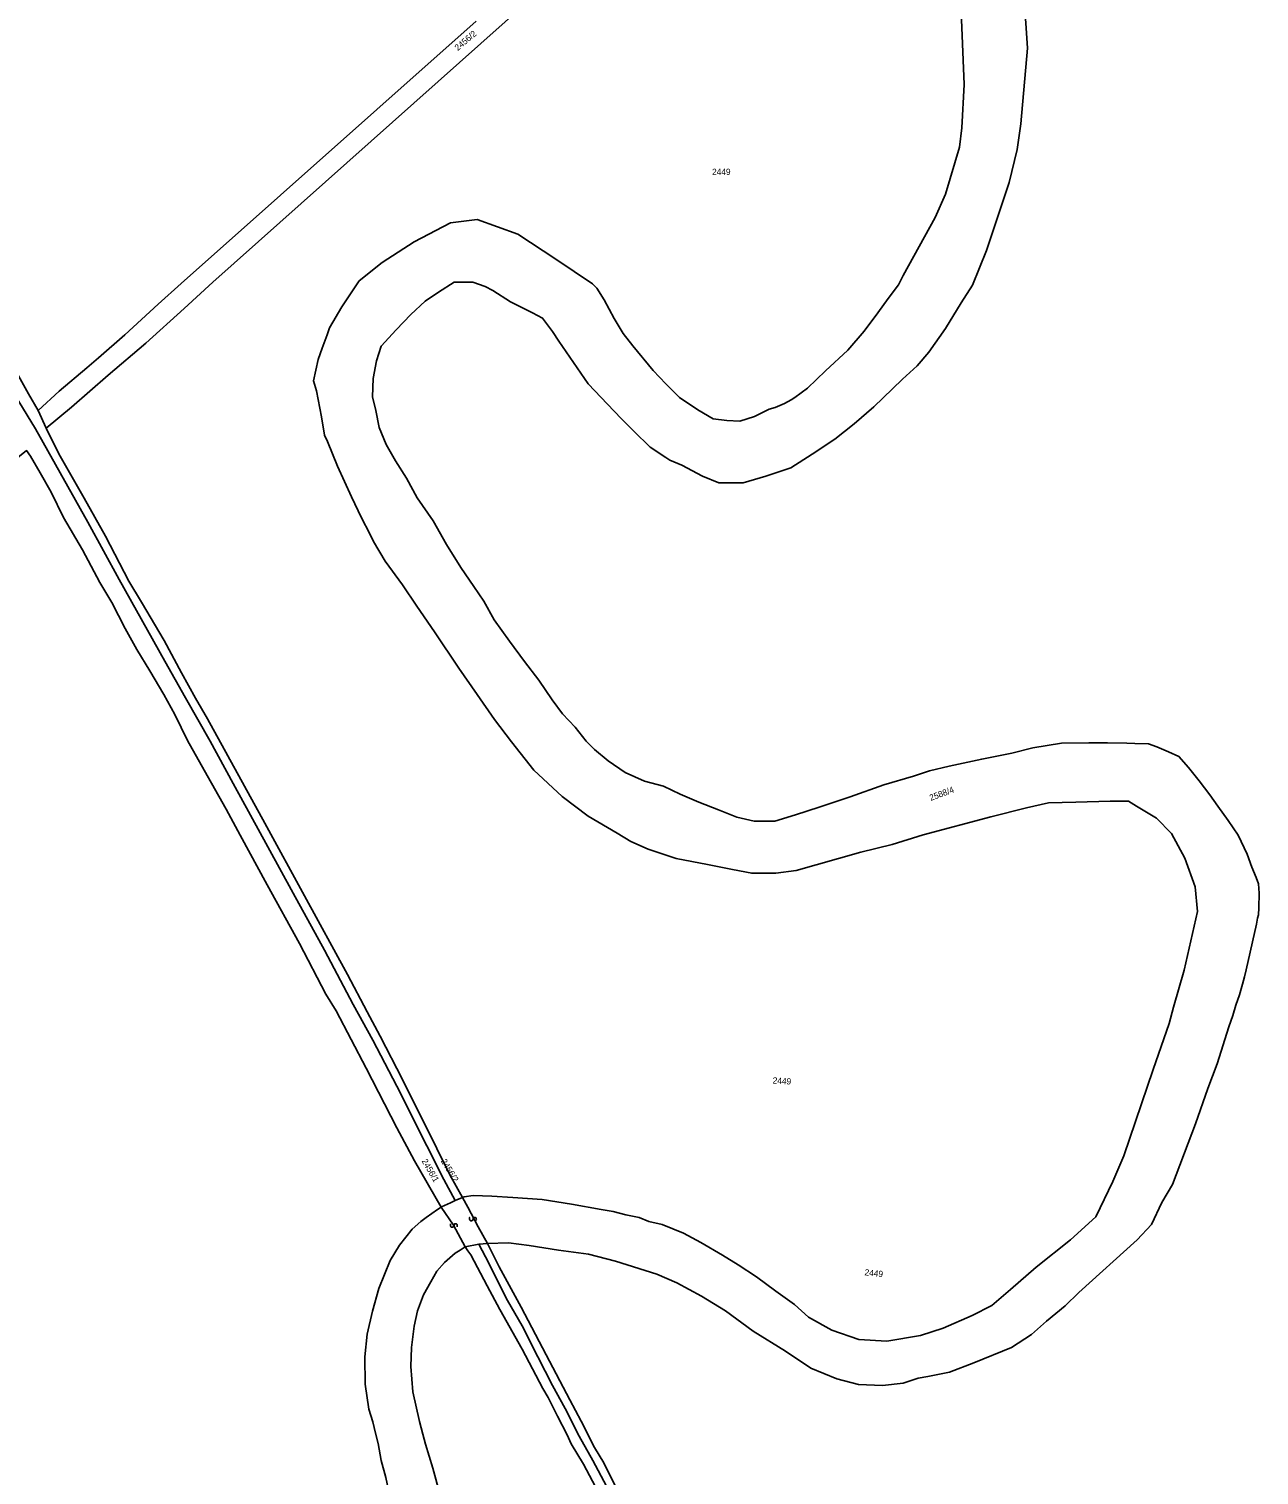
# Model space of a CAD drawing. Extents: x -581999 to -572728, y -1219553 to -1212032.
# Drawn here: x -579464.7 to -579068.9, y -1218458.9 to -1217993.5 of the extents above; entities that cross this region are included whole.
import ezdxf

# ---------------------------------------------------------------- set-up
doc = ezdxf.new("R2010")
doc.units = 0
for name, color, linetype in [('Vrstva 1', 7, 'Continuous'), ('Vrstva 2', 7, 'Continuous'), ('Vrstva 4', 7, 'Continuous'), ('Vrstva 6', 7, 'Continuous')]:
    doc.layers.add(name, color=color, linetype=linetype)

msp = doc.modelspace()

# ---------------------------------------------------------------- linework, layer by layer
at = {"layer": 'Vrstva 1'}
for points in [[(-579161.09, -1218075.938), (-579156.657, -1218064.819), (-579149.279, -1218042.907), (-579146.792, -1218032.236), (-579145.521, -1218023.983), (-579143.409, -1217999.667), (-579144.466, -1217983.535), (-579148.128, -1217948.757), (-579150.946, -1217930.34), (-579153.893, -1217893.376), (-579156.349, -1217870.625), (-579157.124, -1217855.601)], [(-579178.607, -1217874.873), (-579268.374, -1217952.683), (-579405.508, -1218074.987)], [(-579178.607, -1217874.873), (-579177.031, -1217891.385), (-579176.324, -1217904.018), (-579172.693, -1217934.703), (-579172.403, -1217941.208), (-579164.664, -1217990.437), (-579163.787, -1218011.317), (-579164.505, -1218025.247), (-579165.33, -1218031.517), (-579169.824, -1218046.668), (-579173.108, -1218054.19), (-579183.442, -1218072.847), (-579184.956, -1218075.792)], [(-579320.774, -1217990.946), (-579415.781, -1218075.436)], [(-579358.459, -1218074.552), (-579351.068, -1218068.621), (-579340.799, -1218061.98), (-579329.104, -1218055.892), (-579320.546, -1218054.785), (-579307.424, -1218059.49), (-579295.159, -1218067.514), (-579283.394, -1218075.535)], [(-579327.561, -1218370.487), (-579331.193, -1218363.708), (-579336.694, -1218352.936), (-579346.308, -1218333.73), (-579354.031, -1218318.856), (-579360.378, -1218307.469), (-579369.629, -1218289.907), (-579379.679, -1218271.647), (-579387.825, -1218256.67), (-579398.991, -1218236.341), (-579406.396, -1218222.697), (-579414.33, -1218208.746), (-579420.994, -1218196.948), (-579435.645, -1218170.674), (-579445.801, -1218152.209), (-579452.148, -1218140.72), (-579462.574, -1218122.122), (-579471.778, -1218107.042), (-579481.903, -1218087.8), (-579488.885, -1218075.387)], [(-579484.555, -1218075.2), (-579479.794, -1218083.92), (-579472.813, -1218096.64), (-579464.878, -1218110.899), (-579461.705, -1218116.234)], [(-579461.705, -1218116.234), (-579454.984, -1218110.07), (-579446.098, -1218102.581), (-579442.289, -1218099.298), (-579433.826, -1218091.912), (-579423.142, -1218082.064), (-579415.781, -1218075.436)], [(-579405.508, -1218074.987), (-579414.817, -1218083.399), (-579427.088, -1218094.58), (-579439.254, -1218104.839), (-579450.996, -1218115.2), (-579459.173, -1218121.913)], [(-579364.049, -1218082.86), (-579358.459, -1218074.552)], [(-579327.853, -1218074.999), (-579332.976, -1218078.144), (-579337.205, -1218081.073), (-579341.888, -1218085.319), (-579346.57, -1218090.298), (-579351.404, -1218095.57), (-579352.914, -1218100.256), (-579353.972, -1218105.967), (-579354.123, -1218111.824), (-579353.065, -1218116.217), (-579352.008, -1218121.782), (-579349.742, -1218127.2), (-579346.721, -1218132.472), (-579343.247, -1218138.036), (-579339.773, -1218144.333), (-579334.69, -1218151.818), (-579330.31, -1218159.433), (-579325.778, -1218166.755), (-579321.549, -1218172.905), (-579318.377, -1218177.591), (-579315.054, -1218183.595), (-579310.069, -1218190.477), (-579305.236, -1218197.067), (-579300.704, -1218203.071), (-579296.324, -1218209.368), (-579293.001, -1218213.907), (-579288.922, -1218218.154), (-579285.448, -1218222.693), (-579282.729, -1218225.329)], [(-579327.853, -1218074.999), (-579321.87, -1218074.999), (-579317.958, -1218076.338), (-579315.481, -1218077.673)], [(-579224.662, -1218115.246), (-579226.506, -1218115.879), (-579231.311, -1218118.21), (-579235.974, -1218119.718), (-579240.148, -1218119.515), (-579244.528, -1218118.929), (-579249.513, -1218116), (-579255.404, -1218112.047), (-579259.784, -1218107.654), (-579263.863, -1218103.407), (-579270.404, -1218095.45), (-579273.562, -1218091.472), (-579276.446, -1218086.664), (-579279.618, -1218080.66), (-579282.034, -1218076.853), (-579283.394, -1218075.535)], [(-579315.481, -1218077.673), (-579309.742, -1218081.334), (-579302.642, -1218084.849), (-579299.422, -1218086.536), (-579296.298, -1218090.853), (-579294.183, -1218093.928), (-579284.745, -1218107.682), (-579278.552, -1218114.272), (-579274.171, -1218118.811), (-579270.093, -1218122.911), (-579264.806, -1218128.037), (-579259.822, -1218131.405), (-579258.462, -1218132.283), (-579254.686, -1218133.894), (-579248.018, -1218137.384), (-579242.731, -1218139.581), (-579234.877, -1218139.581), (-579227.626, -1218137.384), (-579219.621, -1218134.748), (-579212.673, -1218130.355), (-579205.422, -1218125.523), (-579199.229, -1218120.544), (-579192.885, -1218115.126), (-579186.843, -1218109.268), (-579183.671, -1218106.193), (-579178.914, -1218101.857), (-579175.137, -1218097.464), (-579169.851, -1218089.85), (-579164.715, -1218081.649), (-579161.09, -1218075.938)], [(-579184.956, -1218075.792), (-579188.279, -1218080.185), (-579191.602, -1218084.871), (-579195.982, -1218090.728), (-579201.269, -1218096.879), (-579208.368, -1218103.468), (-579214.259, -1218109.033), (-579218.323, -1218112.099)], [(-579334.272, -1218187.486), (-579339.934, -1218179.228), (-579344.466, -1218172.345), (-579350.055, -1218164.73), (-579353.831, -1218158.434), (-579355.039, -1218155.944), (-579357.758, -1218150.819), (-579360.93, -1218144.083), (-579365.462, -1218134.125), (-579368.634, -1218126.218), (-579369.638, -1218124.155), (-579370.544, -1218118.297), (-579372.206, -1218109.951), (-579373.112, -1218106.728), (-579371.605, -1218099.864), (-579370.393, -1218096.186), (-579368.717, -1218091.861), (-579367.964, -1218089.709), (-579364.049, -1218082.86)], [(-579224.662, -1218115.246), (-579221.647, -1218113.986), (-579219.465, -1218112.782), (-579218.323, -1218112.099)], [(-579461.705, -1218116.234), (-579459.173, -1218121.913)], [(-579459.173, -1218121.913), (-579455.048, -1218130.223), (-579446.902, -1218144.482), (-579440.132, -1218156.69), (-579432.581, -1218171.162), (-579428.455, -1218177.932), (-579421.156, -1218190.243), (-579415.655, -1218200.706), (-579411.106, -1218208.81), (-579407.298, -1218215.478), (-579388.854, -1218249.022), (-579376.054, -1218272.411), (-579362.22, -1218297.772), (-579355.837, -1218309.818)], [(-579498.257, -1218155.71), (-579491.412, -1218150.073), (-579483.055, -1218143.097), (-579474.063, -1218136.019), (-579465.494, -1218129.146), (-579464.225, -1218130.992), (-579461.051, -1218136.327), (-579457.56, -1218142.585), (-579453.541, -1218150.689)], [(-579453.541, -1218150.689), (-579447.478, -1218161.134), (-579441.871, -1218171.598), (-579438.063, -1218178.06), (-579433.726, -1218186.37), (-579430.023, -1218193.14), (-579425.792, -1218200.014)], [(-579176.953, -1218252.865), (-579186.923, -1218255.94), (-579197.043, -1218258.43), (-579211.393, -1218262.53), (-579217.888, -1218264.287), (-579224.429, -1218265.169), (-579232.132, -1218265.169), (-579238.325, -1218263.997), (-579246.331, -1218262.387), (-579256.451, -1218260.483), (-579265.514, -1218257.408), (-579271.103, -1218254.918), (-579275.483, -1218252.282), (-579284.728, -1218246.792), (-579293.186, -1218240.495), (-579302.249, -1218232.002), (-579309.5, -1218222.923), (-579314.938, -1218215.748), (-579320.526, -1218207.694), (-579326.417, -1218199.2), (-579334.272, -1218187.486)], [(-579425.792, -1218200.014), (-579421.309, -1218207.62), (-579417.818, -1218214.083), (-579413.692, -1218222.494), (-579408.297, -1218232.035), (-579401.209, -1218244.55), (-579396.766, -1218252.962), (-579388.101, -1218268.874), (-579377.628, -1218287.749), (-579369.165, -1218304.06), (-579365.885, -1218309.497), (-579356.216, -1218327.88), (-579346.378, -1218347.166), (-579340.665, -1218357.732), (-579332.11, -1218372.641)], [(-579218.063, -1218246.425), (-579210.442, -1218243.934), (-579200.473, -1218240.566), (-579189.597, -1218236.759), (-579180.081, -1218233.977), (-579174.945, -1218232.22), (-579168.601, -1218230.755), (-579158.164, -1218228.459), (-579148.497, -1218226.555), (-579141.7, -1218224.798), (-579132.486, -1218223.334)], [(-579132.486, -1218223.334), (-579123.677, -1218223.176), (-579117.698, -1218223.176), (-579111.488, -1218223.288), (-579108.843, -1218223.399), (-579104.529, -1218223.547), (-579101.769, -1218224.495), (-579098.09, -1218226.113)], [(-579282.729, -1218225.329), (-579278.332, -1218228.999), (-579272.894, -1218232.806), (-579266.701, -1218235.589), (-579260.508, -1218237.2), (-579255.221, -1218239.689), (-579249.179, -1218242.325), (-579242.835, -1218244.814), (-579236.944, -1218247.157), (-579231.356, -1218248.475), (-579224.709, -1218248.475), (-579218.063, -1218246.425)], [(-579098.09, -1218226.113), (-579094.697, -1218227.563), (-579091.593, -1218231.189), (-579088.201, -1218235.484), (-579084.751, -1218239.947), (-579082.221, -1218243.573), (-579078.886, -1218248.259), (-579075.667, -1218252.888), (-579072.706, -1218259.09)], [(-579088.756, -1218277.527), (-579089.488, -1218269.566), (-579092.811, -1218260.341), (-579097.041, -1218252.433), (-579101.874, -1218247.454), (-579108.37, -1218243.647), (-579110.937, -1218242.036), (-579116.828, -1218242.036), (-579127.855, -1218242.329), (-579136.616, -1218242.475), (-579143.715, -1218244.086)], [(-579143.715, -1218244.086), (-579155.202, -1218247.008), (-579176.953, -1218252.865)], [(-579072.706, -1218259.09), (-579071.212, -1218263.273), (-579069.889, -1218266.509), (-579069.142, -1218268.629), (-579068.912, -1218271.641), (-579068.969, -1218276.326), (-579069.142, -1218278.558), (-579069.429, -1218279.673), (-579069.717, -1218281.57), (-579073.047, -1218296.249), (-579073.622, -1218298.564), (-579074.197, -1218300.879)], [(-579097.819, -1218313.55), (-579096.459, -1218308.278), (-579092.985, -1218296.417), (-579090.871, -1218286.898), (-579088.756, -1218277.527)], [(-579074.197, -1218300.879), (-579075.208, -1218304.323), (-579076.377, -1218307.648), (-579077.304, -1218310.935)], [(-579325.193, -1218369.532), (-579329.288, -1218362.267), (-579333.52, -1218353.753), (-579344.518, -1218331.566), (-579351.712, -1218317.615), (-579355.837, -1218309.818)], [(-579077.304, -1218310.935), (-579078.647, -1218314.648)], [(-579213.832, -1218408.054), (-579206.405, -1218412.212), (-579197.644, -1218415.287), (-579188.733, -1218415.726), (-579177.857, -1218413.969), (-579170.607, -1218411.626), (-579161.242, -1218407.526), (-579154.897, -1218404.304), (-579148.855, -1218399.179), (-579140.634, -1218391.93), (-579129.558, -1218383.122), (-579121.418, -1218375.716), (-579115.959, -1218364.366), (-579112.385, -1218356.094), (-579102.955, -1218328.34), (-579097.819, -1218313.55)], [(-579078.647, -1218314.648), (-579082.408, -1218326.541), (-579085.429, -1218334.449), (-579089.356, -1218345.871), (-579096.8, -1218365.328), (-579100.175, -1218371.195), (-579103.55, -1218378.217), (-579108.116, -1218383.122), (-579126.927, -1218400.117)], [(-579280.581, -1218373.374), (-579290.186, -1218371.666), (-579299.578, -1218370.172), (-579308.97, -1218369.532), (-579315.801, -1218369.105), (-579321.777, -1218368.891), (-579324.692, -1218369.357), (-579325.193, -1218369.532)], [(-579332.11, -1218372.641), (-579333.304, -1218373.374), (-579336.933, -1218375.935), (-579338.64, -1218377.216), (-579341.415, -1218379.778), (-579345.471, -1218384.9), (-579348.459, -1218389.81), (-579352.088, -1218398.775)], [(-579327.561, -1218370.487), (-579329.035, -1218371.239), (-579332.004, -1218372.539), (-579332.11, -1218372.641)], [(-579325.193, -1218369.532), (-579327.561, -1218370.487)], [(-579265.212, -1218377.216), (-579268.414, -1218375.935), (-579272.683, -1218375.082), (-579276.739, -1218374.014), (-579280.581, -1218373.374)], [(-579241.519, -1218388.102), (-579248.563, -1218384.047), (-579254.112, -1218381.058), (-579260.943, -1218378.283), (-579265.212, -1218377.216)], [(-579324.408, -1218385.428), (-579325.969, -1218386.493), (-579327.541, -1218387.462), (-579330.956, -1218390.45), (-579333.517, -1218393.225), (-579335.438, -1218396.64), (-579337.786, -1218400.91), (-579339.707, -1218406.032), (-579340.775, -1218410.942), (-579341.629, -1218417.772), (-579341.842, -1218423.963), (-579341.202, -1218432.074), (-579339.067, -1218441.679), (-579338, -1218445.735), (-579337.146, -1218448.937), (-579334.798, -1218456.621), (-579332.45, -1218465.373), (-579330.529, -1218472.203), (-579329.462, -1218476.899), (-579327.754, -1218484.37), (-579326.9, -1218487.785)], [(-579319.922, -1218384.573), (-579324.408, -1218385.428)], [(-579324.408, -1218385.428), (-579323.482, -1218386.661), (-579322.499, -1218388.006), (-579317.295, -1218397.921), (-579313.239, -1218405.605)], [(-579317.146, -1218384.349), (-579319.922, -1218384.573)], [(-579319.922, -1218384.573), (-579317.783, -1218388.664), (-579310.727, -1218402.673), (-579306.042, -1218410.799)], [(-579248.341, -1218401.279), (-579256.239, -1218397.012), (-579262.734, -1218394.23), (-579276.026, -1218389.983), (-579284.636, -1218387.787), (-579294.303, -1218386.469), (-579303.787, -1218384.965), (-579310.438, -1218384.181), (-579317.146, -1218384.349)], [(-579317.146, -1218384.349), (-579313.439, -1218391.858), (-579306.351, -1218404.784), (-579298.311, -1218420.172), (-579290.695, -1218434.636), (-579286.992, -1218441.509)], [(-579241.519, -1218388.102), (-579236.489, -1218391.214), (-579230.599, -1218395.021), (-579224.406, -1218399.707), (-579218.364, -1218403.954), (-579213.832, -1218408.054)], [(-579354.062, -1218441.739), (-579355.33, -1218437.705), (-579356.539, -1218429.651), (-579356.614, -1218420.791), (-579355.859, -1218413.543), (-579354.122, -1218406.075), (-579352.088, -1218398.775)], [(-579204.776, -1218427.854), (-579213.146, -1218424.416), (-579221.303, -1218418.998), (-579231.726, -1218412.555), (-579240.637, -1218405.965), (-579248.341, -1218401.279)], [(-579126.927, -1218400.117), (-579131.308, -1218404.364), (-579137.35, -1218409.342), (-579142.183, -1218413.589), (-579148.527, -1218417.836), (-579160.669, -1218422.729), (-579168.524, -1218425.804), (-579175.472, -1218427.122), (-579178.644, -1218427.708), (-579183.478, -1218429.318), (-579190.124, -1218430.051), (-579197.827, -1218429.758), (-579204.776, -1218427.854)], [(-579313.239, -1218405.605), (-579306.062, -1218418.362), (-579299.353, -1218431.027), (-579297.618, -1218433.941), (-579294.611, -1218439.881), (-579291.487, -1218445.933), (-579290.215, -1218448.847), (-579286.282, -1218455.347)], [(-579306.042, -1218410.799), (-579300.973, -1218420.854), (-579296.213, -1218430.087), (-579292.193, -1218437.473), (-579287.644, -1218446.398), (-579283.307, -1218454.194), (-579278.864, -1218462.401)], [(-579345.684, -1218478.218), (-579346.887, -1218472.857), (-579348.473, -1218466.194), (-579349.833, -1218459.677), (-579351.343, -1218454.186), (-579352.4, -1218448.695), (-579353.156, -1218445.4), (-579354.062, -1218441.739)], [(-579286.992, -1218441.509), (-579282.708, -1218449.952), (-579279.746, -1218454.978), (-579275.303, -1218463.8), (-579270.542, -1218472.828), (-579266.205, -1218480.932), (-579262.82, -1218487.805), (-579259.159, -1218493.957), (-579256.091, -1218499.702), (-579252.495, -1218506.985), (-579249.215, -1218513.243), (-579244.349, -1218521.86), (-579239.8, -1218531.092), (-579236.415, -1218537.248), (-579231.655, -1218545.659), (-579228.75, -1218551.954), (-579225.471, -1218557.698), (-579219.441, -1218567.649), (-579213.411, -1218578.728), (-579210.026, -1218584.986)], [(-579286.282, -1218455.347), (-579278.619, -1218469.718), (-579273.513, -1218479.092), (-579268.317, -1218488.9), (-579264.644, -1218496.278), (-579262.942, -1218499.316), (-579258.175, -1218507.747), (-579253.875, -1218515.732), (-579249.217, -1218524.325), (-579244.559, -1218532.397), (-579240.886, -1218539.948), (-579238.916, -1218543.507), (-579224.928, -1218569.282), (-579214.537, -1218588.551), (-579219.285, -1218592.63)]]:
    msp.add_lwpolyline(points, dxfattribs=at)
at = {"layer": 'Vrstva 4'}
for points in [[(-579332.11, -1218372.641), (-579328.124, -1218378.476), (-579324.408, -1218385.428)], [(-579317.146, -1218384.349), (-579320.19, -1218378.988), (-579323.47, -1218372.628), (-579325.193, -1218369.532)]]:
    msp.add_lwpolyline(points, dxfattribs=at)
at = {"layer": 'Vrstva 6'}
for points in [[(-579326.941, -1218378.987), (-579326.846, -1218378.136), (-579327.576, -1218377.924), (-579327.893, -1218378.178), (-579327.938, -1218378.594), (-579328.089, -1218378.901), (-579328.338, -1218379.068), (-579328.565, -1218379.112), (-579328.828, -1218379.056), (-579329.083, -1218378.792), (-579329.123, -1218378.182), (-579329.053, -1218378.013)], [(-579320.78, -1218376.929), (-579320.685, -1218376.078), (-579321.415, -1218375.866), (-579321.732, -1218376.12), (-579321.777, -1218376.536), (-579321.928, -1218376.843), (-579322.177, -1218377.01), (-579322.404, -1218377.054), (-579322.667, -1218376.998), (-579322.922, -1218376.734), (-579322.962, -1218376.124), (-579322.892, -1218375.955)]]:
    msp.add_open_spline(points, degree=2, dxfattribs=at)

# ---------------------------------------------------------------- texts
at = {"layer": 'Vrstva 2'}
for s, rotation, p in [('2456/2', 40.15293, (-579326.728, -1218000.602)), ('2588/4', 20.32399, (-579174.537, -1218241.929)), ('2449', 356.3704, (-579225.464, -1218332.838)), ('2456/1', 300.24251, (-579338.451, -1218357.793)), ('2456/2', 301.13897, (-579332.262, -1218357.815)), ('2449', 353.96071, (-579195.932, -1218394.568))]:
    msp.add_text(s, height=2, rotation=rotation, dxfattribs=at).set_placement(p)
msp.add_text('2449', height=2, dxfattribs=at).set_placement((-579244.904, -1218040.45))

doc.saveas('drawing.dxf')
